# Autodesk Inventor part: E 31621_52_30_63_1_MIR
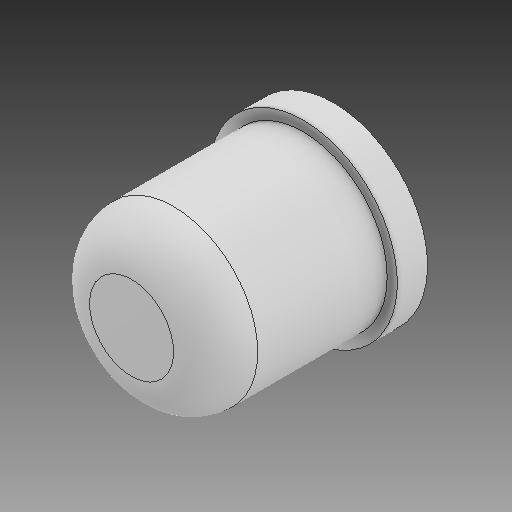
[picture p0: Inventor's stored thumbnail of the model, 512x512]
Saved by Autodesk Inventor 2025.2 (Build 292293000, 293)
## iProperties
Created: 2025-03
Part Number: E 31621_52_30_63_1_MIR
Material: Všeobecné
Description: Pojezd
Document SubType Name: Modeling
Designer: Patrik
Stock Number: Pojezd
Mass: 0.127068 g
Surface Area: 1.42239 cm^2
Volume: 0.127068 cm^3
Density: 1 g/cm^3
Appearance: Výchozí
Author: Patrik
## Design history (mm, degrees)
derived "E 31621_52_30_63_1.ipt"
feature "Těleso1::E 31621_52_30_63_1.ipt" dims "d0" = 10
tag "Prvek štítků1"
node "Těleso1"
